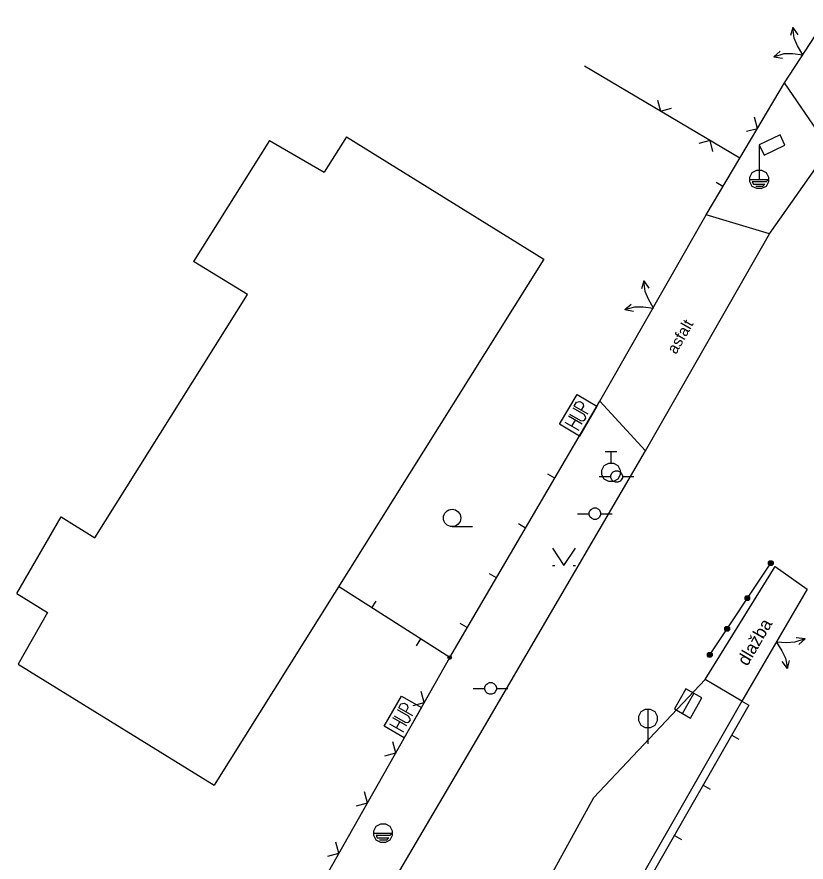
# Model space of a CAD drawing. Extents: x -559554 to -559082, y -1075950 to -1075150.
# Drawn here: x -559154.22 to -559120.03, y -1075199.93 to -1075163.32 of the extents above; entities that cross this region are included whole.
import ezdxf

# ---------------------------------------------------------------- set-up
doc = ezdxf.new("R2010")
doc.units = 0
doc.layers.add('kl', color=7, linetype='Continuous')
doc.layers.add('PF', color=7, linetype='Continuous')

msp = doc.modelspace()

# ---------------------------------------------------------------- linework, layer by layer
at = {"layer": 'kl'}
for p, q in [((-559120.96, -1075166.17), (-559119.11, -1075163.32)), ((-559120.604, -1075163.784), (-559120.71, -1075164.132)), ((-559120.542, -1075164.241), (-559120.604, -1075163.784)), ((-559120.604, -1075163.784), (-559120.392, -1075164.101)), ((-559120.4, -1075164.572), (-559120.542, -1075164.241)), ((-559121.42, -1075165.043), (-559121.146, -1075164.803)), ((-559120.978, -1075164.912), (-559120.617, -1075164.908)), ((-559120.617, -1075164.908), (-559120.173, -1075164.958)), ((-559120.173, -1075164.958), (-559120.4, -1075164.572)), ((-559121.42, -1075165.043), (-559120.978, -1075164.912)), ((-559121.42, -1075165.043), (-559121.045, -1075165.107)), ((-559122.9, -1075169.44), (-559129.632, -1075165.456)), ((-559122.9, -1075169.44), (-559120.96, -1075166.17)), ((-559119.02, -1075169.03), (-559120.96, -1075166.17)), ((-559126.465, -1075166.923), (-559126.342, -1075167.403)), ((-559126.342, -1075167.403), (-559125.863, -1075167.28)), ((-559122.134, -1075168.149), (-559122.257, -1075167.67)), ((-559122.614, -1075168.272), (-559122.134, -1075168.149)), ((-559121.157, -1075168.429), (-559122.06, -1075168.86)), ((-559120.942, -1075168.881), (-559121.157, -1075168.429)), ((-559124.19, -1075168.676), (-559124.67, -1075168.799)), ((-559124.067, -1075169.155), (-559124.19, -1075168.676)), ((-559122.06, -1075168.86), (-559122.06, -1075170.36)), ((-559122.06, -1075168.86), (-559121.845, -1075169.311)), ((-559121.845, -1075169.311), (-559120.942, -1075168.881)), ((-559121.61, -1075172.72), (-559119.02, -1075169.03)), ((-559124.36, -1075171.9), (-559122.9, -1075169.44)), ((-559122.36, -1075170.06), (-559122.16, -1075169.96)), ((-559122.16, -1075169.96), (-559121.96, -1075169.96)), ((-559121.96, -1075169.96), (-559121.76, -1075170.06)), ((-559122.46, -1075170.26), (-559122.36, -1075170.06)), ((-559122.46, -1075170.46), (-559122.46, -1075170.26)), ((-559122.46, -1075170.36), (-559121.66, -1075170.36)), ((-559121.76, -1075170.06), (-559121.66, -1075170.26)), ((-559121.66, -1075170.36), (-559121.76, -1075170.46)), ((-559121.66, -1075170.26), (-559121.66, -1075170.46)), ((-559123.63, -1075170.67), (-559123.93, -1075170.491)), ((-559122.36, -1075170.66), (-559122.46, -1075170.46)), ((-559121.76, -1075170.46), (-559122.36, -1075170.46)), ((-559122.36, -1075170.46), (-559122.31, -1075170.56)), ((-559122.16, -1075170.76), (-559122.36, -1075170.66)), ((-559122.31, -1075170.56), (-559121.81, -1075170.56)), ((-559121.91, -1075170.66), (-559122.21, -1075170.66)), ((-559121.96, -1075170.76), (-559122.16, -1075170.76)), ((-559121.76, -1075170.66), (-559121.96, -1075170.76)), ((-559121.81, -1075170.56), (-559121.91, -1075170.66)), ((-559121.66, -1075170.46), (-559121.76, -1075170.66)), ((-559128.96, -1075179.96), (-559124.36, -1075171.9)), ((-559121.61, -1075172.72), (-559124.36, -1075171.9)), ((-559126.99, -1075182.12), (-559121.61, -1075172.72)), ((-559127.055, -1075174.753), (-559127.166, -1075175.1)), ((-559127, -1075175.211), (-559127.055, -1075174.753)), ((-559127.055, -1075174.753), (-559126.847, -1075175.072)), ((-559126.861, -1075175.544), (-559127, -1075175.211)), ((-559127.888, -1075176), (-559127.61, -1075175.765)), ((-559127.888, -1075176), (-559127.444, -1075175.876)), ((-559127.444, -1075175.876), (-559127.083, -1075175.876)), ((-559127.083, -1075175.876), (-559126.64, -1075175.932)), ((-559126.64, -1075175.932), (-559126.861, -1075175.544)), ((-559127.888, -1075176), (-559127.513, -1075176.07)), ((-559130.71, -1075180.969), (-559129.952, -1075179.675)), ((-559129.952, -1075179.675), (-559129.089, -1075180.181)), ((-559135.47, -1075191.07), (-559128.96, -1075179.96)), ((-559129.651, -1075180.547), (-559130.126, -1075180.269)), ((-559130.075, -1075180.182), (-559129.974, -1075180.01)), ((-559129.471, -1075180.536), (-559130.075, -1075180.182)), ((-559129.974, -1075180.01), (-559129.837, -1075179.974)), ((-559129.089, -1075180.181), (-559129.847, -1075181.475)), ((-559129.837, -1075179.974), (-559129.708, -1075180.05)), ((-559129.672, -1075180.187), (-559129.773, -1075180.359)), ((-559129.708, -1075180.05), (-559129.672, -1075180.187)), ((-559126.99, -1075182.12), (-559128.96, -1075179.96)), ((-559129.724, -1075180.968), (-559130.328, -1075180.614)), ((-559130.277, -1075180.527), (-559129.803, -1075180.806)), ((-559129.59, -1075180.64), (-559129.651, -1075180.547)), ((-559129.572, -1075180.709), (-559129.59, -1075180.64)), ((-559129.847, -1075181.475), (-559130.71, -1075180.969)), ((-559130.48, -1075180.873), (-559129.876, -1075181.226)), ((-559130.178, -1075181.05), (-559130.026, -1075180.791)), ((-559129.803, -1075180.806), (-559129.691, -1075180.813)), ((-559129.691, -1075180.813), (-559129.623, -1075180.795)), ((-559129.623, -1075180.795), (-559129.572, -1075180.709)), ((-559134.17, -1075194.41), (-559126.99, -1075182.12)), ((-559128.73, -1075182.15), (-559128.23, -1075182.15)), ((-559128.48, -1075182.65), (-559128.48, -1075182.15)), ((-559128.88, -1075182.95), (-559128.78, -1075182.75)), ((-559128.78, -1075182.75), (-559128.58, -1075182.65)), ((-559128.58, -1075182.65), (-559128.38, -1075182.65)), ((-559128.38, -1075182.65), (-559128.18, -1075182.75)), ((-559128.18, -1075182.75), (-559128.08, -1075182.95)), ((-559130.919, -1075183.304), (-559131.221, -1075183.127)), ((-559128.88, -1075183.15), (-559128.88, -1075182.95)), ((-559128.78, -1075183.35), (-559128.88, -1075183.15)), ((-559128.49, -1075183.18), (-559128.44, -1075183.08)), ((-559128.49, -1075183.28), (-559128.49, -1075183.18)), ((-559128.44, -1075183.08), (-559128.39, -1075183.03)), ((-559128.39, -1075183.03), (-559128.29, -1075182.98)), ((-559128.29, -1075182.98), (-559128.19, -1075182.98)), ((-559128.19, -1075182.98), (-559128.09, -1075183.03)), ((-559128.08, -1075183.15), (-559128.18, -1075183.35)), ((-559128.09, -1075183.03), (-559128.04, -1075183.08)), ((-559128.08, -1075182.95), (-559128.08, -1075183.15)), ((-559128.04, -1075183.08), (-559127.99, -1075183.18)), ((-559127.99, -1075183.18), (-559127.99, -1075183.28)), ((-559128.99, -1075183.23), (-559128.49, -1075183.23)), ((-559128.58, -1075183.45), (-559128.78, -1075183.35)), ((-559128.38, -1075183.45), (-559128.58, -1075183.45)), ((-559128.44, -1075183.38), (-559128.49, -1075183.28)), ((-559128.39, -1075183.43), (-559128.44, -1075183.38)), ((-559128.29, -1075183.48), (-559128.39, -1075183.43)), ((-559128.18, -1075183.35), (-559128.38, -1075183.45)), ((-559128.19, -1075183.48), (-559128.29, -1075183.48)), ((-559128.09, -1075183.43), (-559128.19, -1075183.48)), ((-559128.04, -1075183.38), (-559128.09, -1075183.43)), ((-559127.99, -1075183.28), (-559128.04, -1075183.38)), ((-559127.99, -1075183.23), (-559127.49, -1075183.23)), ((-559129.38, -1075184.69), (-559129.33, -1075184.64)), ((-559129.33, -1075184.64), (-559129.23, -1075184.59)), ((-559129.23, -1075184.59), (-559129.13, -1075184.59)), ((-559129.13, -1075184.59), (-559129.03, -1075184.64)), ((-559129.03, -1075184.64), (-559128.98, -1075184.69)), ((-559129.93, -1075184.84), (-559129.43, -1075184.84)), ((-559129.43, -1075184.79), (-559129.38, -1075184.69)), ((-559129.43, -1075184.89), (-559129.43, -1075184.79)), ((-559129.38, -1075184.99), (-559129.43, -1075184.89)), ((-559129.33, -1075185.04), (-559129.38, -1075184.99)), ((-559129.23, -1075185.09), (-559129.33, -1075185.04)), ((-559129.03, -1075185.04), (-559129.13, -1075185.09)), ((-559128.98, -1075184.99), (-559129.03, -1075185.04)), ((-559128.98, -1075184.69), (-559128.93, -1075184.79)), ((-559128.93, -1075184.89), (-559128.98, -1075184.99)), ((-559128.93, -1075184.79), (-559128.93, -1075184.89)), ((-559128.93, -1075184.84), (-559128.43, -1075184.84)), ((-559135.365, -1075185.401), (-559134.49, -1075185.401)), ((-559132.183, -1075185.461), (-559132.485, -1075185.284)), ((-559129.13, -1075185.09), (-559129.23, -1075185.09)), ((-559131.02, -1075186.328), (-559130.52, -1075187.078)), ((-559130.52, -1075187.078), (-559130.02, -1075186.328)), ((-559131.02, -1075187.078), (-559130.92, -1075187.078)), ((-559130.12, -1075187.078), (-559130.02, -1075187.078)), ((-559124.4, -1075192.03), (-559121.37, -1075187.13)), ((-559124.2, -1075190.95), (-559121.56, -1075186.98)), ((-559121.66, -1075186.93), (-559121.61, -1075186.88)), ((-559121.66, -1075187.03), (-559121.66, -1075186.93)), ((-559121.61, -1075187.08), (-559121.66, -1075187.03)), ((-559121.61, -1075186.88), (-559121.51, -1075186.88)), ((-559121.61, -1075187.03), (-559121.61, -1075186.93)), ((-559121.61, -1075186.93), (-559121.51, -1075186.93)), ((-559121.61, -1075187.03), (-559121.51, -1075186.93)), ((-559121.51, -1075187.03), (-559121.61, -1075187.03)), ((-559121.51, -1075187.08), (-559121.61, -1075187.08)), ((-559121.51, -1075186.88), (-559121.46, -1075186.93)), ((-559121.51, -1075186.93), (-559121.51, -1075187.03)), ((-559121.46, -1075187.03), (-559121.51, -1075187.08)), ((-559121.46, -1075186.93), (-559121.46, -1075187.03)), ((-559121.37, -1075187.13), (-559119.98, -1075188.11)), ((-559133.447, -1075187.618), (-559133.749, -1075187.441)), ((-559135.47, -1075191.07), (-559140.288, -1075187.999)), ((-559119.98, -1075188.11), (-559122.81, -1075192.96)), ((-559138.843, -1075188.92), (-559138.655, -1075188.625)), ((-559122.674, -1075188.455), (-559122.624, -1075188.405)), ((-559122.674, -1075188.555), (-559122.674, -1075188.455)), ((-559122.624, -1075188.605), (-559122.674, -1075188.555)), ((-559122.624, -1075188.405), (-559122.524, -1075188.405)), ((-559122.624, -1075188.555), (-559122.624, -1075188.455)), ((-559122.624, -1075188.455), (-559122.524, -1075188.455)), ((-559122.624, -1075188.555), (-559122.524, -1075188.455)), ((-559122.524, -1075188.555), (-559122.624, -1075188.555)), ((-559122.524, -1075188.605), (-559122.624, -1075188.605)), ((-559122.524, -1075188.405), (-559122.474, -1075188.455)), ((-559122.524, -1075188.455), (-559122.524, -1075188.555)), ((-559122.474, -1075188.555), (-559122.524, -1075188.605)), ((-559122.474, -1075188.455), (-559122.474, -1075188.555)), ((-559134.711, -1075189.775), (-559135.013, -1075189.598)), ((-559123.55, -1075189.773), (-559123.5, -1075189.723)), ((-559123.55, -1075189.873), (-559123.55, -1075189.773)), ((-559123.5, -1075189.723), (-559123.4, -1075189.723)), ((-559123.5, -1075189.873), (-559123.5, -1075189.773)), ((-559123.5, -1075189.773), (-559123.4, -1075189.773)), ((-559123.5, -1075189.873), (-559123.4, -1075189.773)), ((-559123.4, -1075189.723), (-559123.35, -1075189.773)), ((-559123.4, -1075189.773), (-559123.4, -1075189.873)), ((-559123.35, -1075189.773), (-559123.35, -1075189.873)), ((-559123.5, -1075189.923), (-559123.55, -1075189.873)), ((-559123.4, -1075189.873), (-559123.5, -1075189.873)), ((-559123.4, -1075189.923), (-559123.5, -1075189.923)), ((-559123.35, -1075189.873), (-559123.4, -1075189.923)), ((-559136.735, -1075190.263), (-559136.923, -1075190.559)), ((-559120.871, -1075190.43), (-559121.317, -1075190.401)), ((-559121.317, -1075190.401), (-559121.072, -1075190.776)), ((-559120.511, -1075190.409), (-559120.871, -1075190.43)), ((-559120.075, -1075190.258), (-559120.511, -1075190.409)), ((-559120.075, -1075190.258), (-559120.453, -1075190.211)), ((-559120.075, -1075190.258), (-559120.338, -1075190.51)), ((-559124.3, -1075190.9), (-559124.25, -1075190.85)), ((-559124.3, -1075191), (-559124.3, -1075190.9)), ((-559124.25, -1075190.85), (-559124.15, -1075190.85)), ((-559124.25, -1075191), (-559124.25, -1075190.9)), ((-559124.25, -1075190.9), (-559124.15, -1075190.9)), ((-559124.25, -1075191), (-559124.15, -1075190.9)), ((-559124.15, -1075190.85), (-559124.1, -1075190.9)), ((-559124.15, -1075190.9), (-559124.15, -1075191)), ((-559124.1, -1075190.9), (-559124.1, -1075191)), ((-559121.072, -1075190.776), (-559120.914, -1075191.1)), ((-559141.01, -1075200.85), (-559135.47, -1075191.07)), ((-559135.525, -1075191.069), (-559135.514, -1075191.047)), ((-559135.436, -1075191.115), (-559135.525, -1075191.069)), ((-559135.515, -1075191.103), (-559135.47, -1075191.126)), ((-559135.514, -1075191.047), (-559135.425, -1075191.092)), ((-559135.502, -1075191.025), (-559135.469, -1075191.014)), ((-559135.413, -1075191.07), (-559135.502, -1075191.025)), ((-559135.47, -1075191.126), (-559135.436, -1075191.115)), ((-559135.469, -1075191.014), (-559135.424, -1075191.037)), ((-559135.425, -1075191.092), (-559135.413, -1075191.07)), ((-559124.25, -1075191.05), (-559124.3, -1075191)), ((-559124.15, -1075191), (-559124.25, -1075191)), ((-559124.15, -1075191.05), (-559124.25, -1075191.05)), ((-559124.1, -1075191), (-559124.15, -1075191.05)), ((-559120.831, -1075191.553), (-559121.058, -1075191.247)), ((-559120.914, -1075191.1), (-559120.831, -1075191.553)), ((-559120.831, -1075191.553), (-559120.741, -1075191.201)), ((-559133.95, -1075192.36), (-559133.9, -1075192.26)), ((-559133.95, -1075192.46), (-559133.95, -1075192.36)), ((-559133.9, -1075192.26), (-559133.85, -1075192.21)), ((-559133.85, -1075192.21), (-559133.75, -1075192.16)), ((-559133.75, -1075192.16), (-559133.65, -1075192.16)), ((-559133.65, -1075192.16), (-559133.55, -1075192.21)), ((-559133.55, -1075192.21), (-559133.5, -1075192.26)), ((-559133.5, -1075192.26), (-559133.45, -1075192.36)), ((-559133.45, -1075192.36), (-559133.45, -1075192.46)), ((-559129.23, -1075197.14), (-559124.4, -1075192.03)), ((-559122.81, -1075192.96), (-559124.4, -1075192.03)), ((-559136.574, -1075193.019), (-559136.706, -1075192.542)), ((-559134.45, -1075192.41), (-559133.95, -1075192.41)), ((-559133.9, -1075192.56), (-559133.95, -1075192.46)), ((-559133.85, -1075192.61), (-559133.9, -1075192.56)), ((-559133.75, -1075192.66), (-559133.85, -1075192.61)), ((-559133.65, -1075192.66), (-559133.75, -1075192.66)), ((-559133.55, -1075192.61), (-559133.65, -1075192.66)), ((-559133.5, -1075192.56), (-559133.55, -1075192.61)), ((-559133.45, -1075192.46), (-559133.5, -1075192.56)), ((-559133.45, -1075192.41), (-559132.95, -1075192.41)), ((-559125.238, -1075192.427), (-559125.735, -1075193.295)), ((-559125.388, -1075193.493), (-559124.891, -1075192.626)), ((-559124.544, -1075192.824), (-559125.238, -1075192.427)), ((-559138.309, -1075194.046), (-559137.564, -1075192.744)), ((-559137.682, -1075193.253), (-559137.583, -1075193.079)), ((-559137.583, -1075193.079), (-559137.446, -1075193.042)), ((-559137.564, -1075192.744), (-559136.696, -1075193.241)), ((-559137.446, -1075193.042), (-559137.316, -1075193.117)), ((-559137.051, -1075193.151), (-559136.574, -1075193.019)), ((-559122.81, -1075192.96), (-559129.19, -1075204.1)), ((-559125.041, -1075193.692), (-559124.544, -1075192.824)), ((-559122.81, -1075192.96), (-559122.506, -1075193.133)), ((-559137.254, -1075193.613), (-559137.732, -1075193.34)), ((-559137.074, -1075193.6), (-559137.682, -1075193.253)), ((-559136.696, -1075193.241), (-559137.441, -1075194.543)), ((-559137.279, -1075193.253), (-559137.378, -1075193.427)), ((-559137.316, -1075193.117), (-559137.279, -1075193.253)), ((-559122.506, -1075193.133), (-559128.887, -1075204.275)), ((-559127.28, -1075193.61), (-559127.18, -1075193.41)), ((-559127.18, -1075193.41), (-559126.98, -1075193.31)), ((-559126.98, -1075193.31), (-559126.78, -1075193.31)), ((-559126.88, -1075193.31), (-559126.88, -1075194.81)), ((-559126.78, -1075193.31), (-559126.58, -1075193.41)), ((-559126.58, -1075193.41), (-559126.48, -1075193.61)), ((-559125.735, -1075193.295), (-559125.041, -1075193.692)), ((-559137.323, -1075194.034), (-559137.93, -1075193.687)), ((-559137.881, -1075193.6), (-559137.403, -1075193.873)), ((-559137.192, -1075193.706), (-559137.254, -1075193.613)), ((-559137.223, -1075193.861), (-559137.174, -1075193.774)), ((-559137.174, -1075193.774), (-559137.192, -1075193.706)), ((-559127.28, -1075193.81), (-559127.28, -1075193.61)), ((-559127.18, -1075194.01), (-559127.28, -1075193.81)), ((-559126.48, -1075193.81), (-559126.58, -1075194.01)), ((-559126.48, -1075193.61), (-559126.48, -1075193.81)), ((-559137.441, -1075194.543), (-559138.309, -1075194.046)), ((-559138.079, -1075193.947), (-559137.472, -1075194.295)), ((-559137.775, -1075194.121), (-559137.626, -1075193.861)), ((-559137.403, -1075193.873), (-559137.292, -1075193.879)), ((-559137.292, -1075193.879), (-559137.223, -1075193.861)), ((-559126.98, -1075194.11), (-559127.18, -1075194.01)), ((-559126.78, -1075194.11), (-559126.98, -1075194.11)), ((-559126.58, -1075194.01), (-559126.78, -1075194.11)), ((-559138.66, -1075202.05), (-559134.17, -1075194.41)), ((-559123.251, -1075194.435), (-559122.948, -1075194.609)), ((-559137.806, -1075195.194), (-559137.938, -1075194.717)), ((-559138.283, -1075195.326), (-559137.806, -1075195.194)), ((-559124.494, -1075196.605), (-559124.19, -1075196.778)), ((-559139.038, -1075197.369), (-559139.17, -1075196.892)), ((-559140.82, -1075218.19), (-559129.23, -1075197.14)), ((-559139.515, -1075197.501), (-559139.038, -1075197.369)), ((-559138.76, -1075198.58), (-559138.66, -1075198.38)), ((-559138.76, -1075198.78), (-559138.76, -1075198.58)), ((-559138.66, -1075198.38), (-559138.46, -1075198.28)), ((-559138.46, -1075198.28), (-559138.26, -1075198.28)), ((-559138.26, -1075198.28), (-559138.06, -1075198.38)), ((-559138.06, -1075198.38), (-559137.96, -1075198.58)), ((-559137.96, -1075198.58), (-559137.96, -1075198.78)), ((-559138.76, -1075198.68), (-559137.96, -1075198.68)), ((-559138.66, -1075198.98), (-559138.76, -1075198.78)), ((-559138.06, -1075198.78), (-559138.66, -1075198.78)), ((-559138.66, -1075198.78), (-559138.61, -1075198.88)), ((-559138.61, -1075198.88), (-559138.11, -1075198.88)), ((-559138.11, -1075198.88), (-559138.21, -1075198.98)), ((-559137.96, -1075198.68), (-559138.06, -1075198.78)), ((-559137.96, -1075198.78), (-559138.06, -1075198.98)), ((-559125.736, -1075198.774), (-559125.432, -1075198.948)), ((-559140.27, -1075199.544), (-559140.402, -1075199.067)), ((-559138.46, -1075199.08), (-559138.66, -1075198.98)), ((-559138.21, -1075198.98), (-559138.51, -1075198.98)), ((-559138.26, -1075199.08), (-559138.46, -1075199.08)), ((-559138.06, -1075198.98), (-559138.26, -1075199.08)), ((-559140.747, -1075199.676), (-559140.27, -1075199.544))]:
    msp.add_line(p, q, dxfattribs=at)
for centre, radius in [((-559135.366, -1075185.026), 0.375), ((-559135.47, -1075191.07), 0.075)]:
    msp.add_circle(centre, radius, dxfattribs=at)
at = {"layer": 'PF'}
for p, q in [((-559139.941, -1075168.509), (-559140.909, -1075170.04)), ((-559139.941, -1075168.509), (-559131.389, -1075173.809)), ((-559143.279, -1075168.669), (-559146.569, -1075173.919)), ((-559143.279, -1075168.669), (-559140.909, -1075170.04)), ((-559144.229, -1075175.35), (-559146.569, -1075173.919)), ((-559131.389, -1075173.809), (-559145.681, -1075196.599)), ((-559150.849, -1075185.89), (-559144.229, -1075175.35)), ((-559154.225, -1075188.291), (-559152.313, -1075184.972)), ((-559152.313, -1075184.972), (-559150.849, -1075185.89)), ((-559154.225, -1075188.291), (-559152.902, -1075189.116)), ((-559152.902, -1075189.116), (-559154.165, -1075191.362)), ((-559154.165, -1075191.362), (-559145.681, -1075196.599))]:
    msp.add_line(p, q, dxfattribs=at)

# ---------------------------------------------------------------- texts
at = {"layer": 'kl'}
for s, height, rotation, p in [('asfalt', 0.4875, 60.2157, (-559125.666, -1075177.963)), ('dlažba', 0.5525, 59.7362, (-559122.57, -1075191.475))]:
    msp.add_text(s, height=height, rotation=rotation, dxfattribs=at).set_placement(p)

doc.saveas('drawing.dxf')
